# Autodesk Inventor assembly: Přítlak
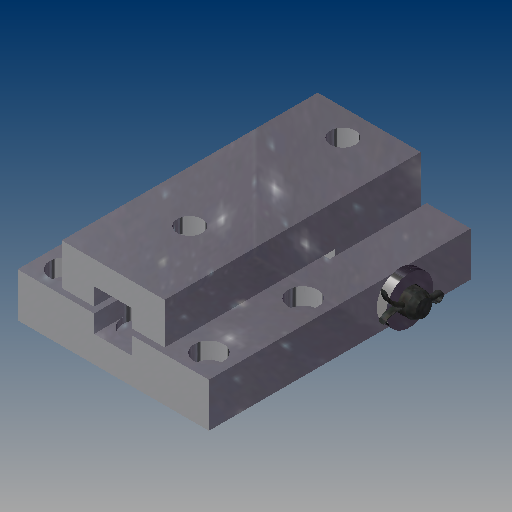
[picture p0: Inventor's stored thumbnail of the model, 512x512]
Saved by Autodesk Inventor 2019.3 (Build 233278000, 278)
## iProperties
Created: 2019-01
Part Number: Přítlak
Material: Všeobecné
Document SubType Name: Assembly
Designer: B-hon
Author: B-hon
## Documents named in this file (7)
- C:\Users\B-hon\OneDrive\Plocha\Bakalářka22\Přítlak spodní\Pravý\Přítlak4s.iam
- C:\Users\B-hon\OneDrive\Plocha\Bakalářka22\Přítlak spodní\Pravý\Příruba vozíku4s.ipt
- C:\Users\B-hon\OneDrive\Plocha\Bakalářka22\Přítlak spodní\Pravý\Příruba desky4s.ipt
- C:\Users\B-hon\OneDrive\Documents\Inventor\Content Center Files\R2019\cs-CZ\BS EN 22 341  B\ISO 2341 - B - 8 x 70BS EN.ipt
- C:\Users\B-hon\OneDrive\Documents\Inventor\Content Center Files\R2019\cs-CZ\CSN EN ISO 1234\CSN EN ISO 1234 - 2x16 x 10 - 9.ipt
- C:\Users\B-hon\OneDrive\Documents\Inventor\Content Center Files\R2019\cs-CZ\CSN EN ISO 2338\ISO 2338 - 6 h8 x 20CSN EN.ipt
- C:\Users\B-hon\OneDrive\Documents\Inventor\Content Center Files\R2019\cs-CZ\DIN 125-1  A\DIN 125 - A 8,4.ipt
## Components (7 placed, 6 different names)
1. Příruba vozíku4s:1 — Vložit:1, Úhel:1, Vložit:6, Vložit:7
2. Příruba desky4s:1 — Vložit:1, Úhel:1, Vložit:3
3. CSN EN ISO 1234 2x16:1 — Proti sobě:3
4. CSN EN ISO 2338 6 h8 x 20:1 — Vložit:3
5. BS EN 22341 B B - 8 x 70:1 — Proti sobě:3, Vložit:7
6. DIN 125-1 A A 8,4:1 — Vložit:5
7. DIN 125-1 A A 8,4:2 — Vložit:5, Vložit:6
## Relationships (7: Insert 5, Angle 1, Mate 1)
- Vložit:1 [Insert]: Příruba vozíku4s:1 ↔ Příruba desky4s:1
- Úhel:1 [Angle]: Příruba vozíku4s:1 ↔ Příruba desky4s:1
- Vložit:3 [Insert]: Příruba desky4s:1 ↔ CSN EN ISO 2338 6 h8 x 20:1
- Vložit:5 [Insert]: DIN 125-1 A A 8,4:1 ↔ DIN 125-1 A A 8,4:2
- Vložit:6 [Insert]: Příruba vozíku4s:1 ↔ DIN 125-1 A A 8,4:2
- Proti sobě:3 [Mate]: CSN EN ISO 1234 2x16:1 ↔ BS EN 22341 B B - 8 x 70:1
- Vložit:7 [Insert]: Příruba vozíku4s:1 ↔ BS EN 22341 B B - 8 x 70:1
